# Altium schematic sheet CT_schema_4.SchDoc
size 282 x 169 mm
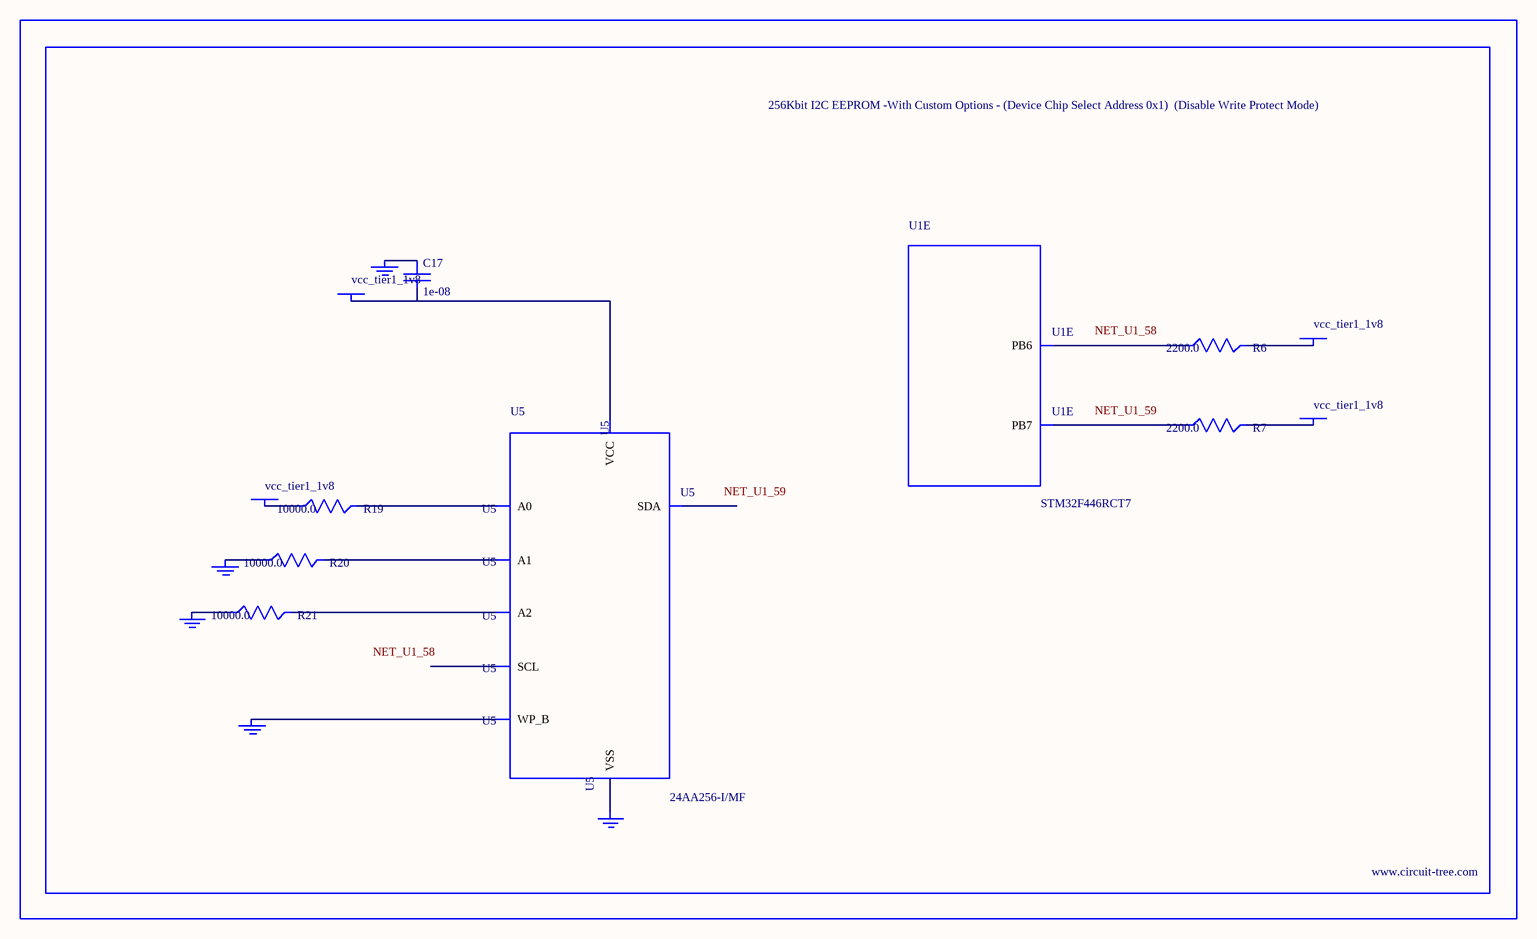
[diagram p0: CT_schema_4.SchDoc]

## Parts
BORDER3  (no value)
C17  1e-08  [C0402]
GND_INSTANCE_3_0  (no value)
GND_INSTANCE_3_1  (no value)
GND_INSTANCE_3_2  (no value)
GND_INSTANCE_3_3  (no value)
GND_INSTANCE_3_4  (no value)
POWER_INSTANCE_3_0  vcc_tier1_1v8
POWER_INSTANCE_3_1  vcc_tier1_1v8
POWER_INSTANCE_3_2  vcc_tier1_1v8
POWER_INSTANCE_3_3  vcc_tier1_1v8
R6  2200.0  [R0603]
R7  2200.0  [R0603]
R19  10000.0  [R0603]
R20  10000.0  [R0603]
R21  10000.0  [R0603]
U1  STM32F446RCT7  [LQFP64]  (part E of 7)
U5  24AA256-I/MF  [DFN8-S]

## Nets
NetC17_1: C17.1 GND_INSTANCE_3_3.0(GND)
NetC17_2: C17.2 POWER_INSTANCE_3_1.0(PWR) U5.8(VCC)
NetGND_INSTANCE_3_0_0: GND_INSTANCE_3_0.0(GND) R20.1
NetGND_INSTANCE_3_1_0: GND_INSTANCE_3_1.0(GND) R21.1
NetGND_INSTANCE_3_2_0: GND_INSTANCE_3_2.0(GND) U5.7(WP_B)
NetGND_INSTANCE_3_4_0: GND_INSTANCE_3_4.0(GND) U5.4(VSS)
NetPOWER_INSTANCE_3_0_0: POWER_INSTANCE_3_0.0(PWR) R19.1
NetPOWER_INSTANCE_3_2_0: POWER_INSTANCE_3_2.0(PWR) R6.2
NetPOWER_INSTANCE_3_3_0: POWER_INSTANCE_3_3.0(PWR) R7.2
NetR6_1: R6.1 U1.58(PB6)
NetR7_1: R7.1 U1.59(PB7)
NetR19_2: R19.2 U5.1(A0)
NetR20_2: R20.2 U5.2(A1)
NetR21_2: R21.2 U5.3(A2)

Not connected (* = marked no-connect by the designer): U5 5(SDA) 6(SCL)

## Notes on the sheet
- Labels drawn without touching a wire or pin: NET_U1_58, NET_U1_59

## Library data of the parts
BORDER3 = BORDER_PAGE3
C17 = C0402C103K3RAC
GND_INSTANCE_3_0-GND_INSTANCE_3_4 = GND
POWER_INSTANCE_3_0-POWER_INSTANCE_3_3 = PWR
R6 R7 = RC0603JR-072K2L
R19-R21 = RC0603JR-0710KL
